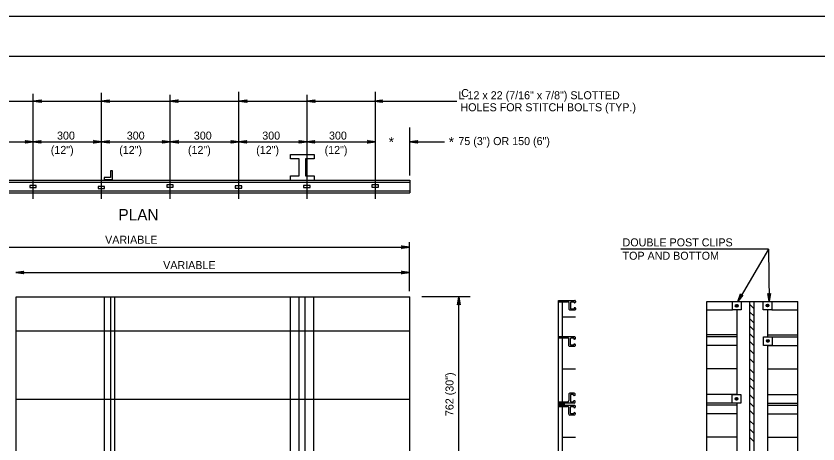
# Model space of a CAD drawing. Extents: x 647822 to 648727, y 298458 to 299646.
# Drawn here: x 647981.4 to 648281.8, y 299485.4 to 299645.6 of the extents above; entities that cross this region are included whole.
import ezdxf

# ---------------------------------------------------------------- set-up
doc = ezdxf.new("R2010")
doc.units = 0
for name, color, linetype in [('1', 7, 'Continuous'), ('2', 7, 'Continuous'), ('3', 7, 'Continuous'), ('XCS-GRID-MIN', 7, 'Continuous')]:
    doc.layers.add(name, color=color, linetype=linetype)

# ---------------------------------------------------------------- blocks, each defined once
blk = doc.blocks.new('RARROW')
at = {"layer": '3'}
blk.add_lwpolyline([(-2.2695, 0.285), (-2.184875, 0.12075), (0, 0), (-2.2695, 0.285), (-2.38575, 0.384625), (0, 0), (-2.183125, -0.108), (-2.262875, -0.2705), (0, 0), (-2.38575, -0.379125), (-2.262875, -0.2705)], dxfattribs=at)

msp = doc.modelspace()

# ---------------------------------------------------------------- linework, layer by layer
at = {"layer": '1'}
msp.add_line((647862.31, 299630.63), (648648.31, 299630.63), dxfattribs=at)
at = {"layer": '2'}
for p, q in [((647987.88, 299577.1), (647987.88, 299616.48)), ((648013.5, 299577.1), (648013.5, 299616.85)), ((648039.13, 299577.1), (648039.13, 299616.1)), ((648064.88, 299577.1), (648064.88, 299617.23)), ((648090.5, 299577.1), (648090.5, 299616.1)), ((648116.13, 299577.1), (648116.13, 299617.23)), ((647962.25, 299613.73), (647987.88, 299613.73)), ((647988, 299613.73), (648013.5, 299613.73)), ((647988, 299613.73), (647988, 299613.73)), ((648013.5, 299613.73), (648039.13, 299613.73)), ((648013.5, 299613.73), (648013.5, 299613.73)), ((648039.13, 299613.73), (648064.88, 299613.73)), ((648039.13, 299613.73), (648039.13, 299613.73)), ((648065, 299613.73), (648090.5, 299613.73)), ((648065, 299613.73), (648065, 299613.73)), ((648090.5, 299613.73), (648115.75, 299613.73)), ((648090.5, 299613.73), (648090.5, 299613.73)), ((648115.75, 299613.73), (648146.5, 299613.73)), ((648115.75, 299613.73), (648115.75, 299613.73)), ((648129, 299585.85), (648129, 299603.85)), ((647962.38, 299598.48), (647987.88, 299598.48)), ((647987.88, 299598.48), (648013.5, 299598.48)), ((648013.5, 299598.48), (648039.13, 299598.48)), ((648039.25, 299598.48), (648064.88, 299598.48)), ((648064.88, 299598.48), (648090.38, 299598.48)), ((648090.38, 299598.48), (648116.13, 299598.48)), ((648129, 299598.48), (648141.88, 299598.48)), ((648084.25, 299592.1), (648084.25, 299593.73)), ((648084.25, 299593.73), (648093.13, 299593.73)), ((648087.5, 299592.1), (648084.25, 299592.1)), ((648087.5, 299585.73), (648087.5, 299592.1)), ((648093.13, 299592.1), (648089.88, 299592.1)), ((648089.88, 299592.1), (648089.88, 299585.73)), ((648093.13, 299593.73), (648093.13, 299592.1)), ((648017.63, 299587.6), (648016.88, 299587.6)), ((648016.88, 299587.6), (648016.88, 299585.1)), ((648017.63, 299584.35), (648017.63, 299587.6)), ((647923.75, 299584.1), (648129, 299584.1)), ((647923.75, 299583.35), (648129, 299583.35)), ((648014.5, 299585.1), (648014.5, 299584.35)), ((648016.88, 299585.1), (648014.5, 299585.1)), ((648014.5, 299584.35), (648017.63, 299584.35)), ((648084.25, 299584.1), (648084.25, 299585.73)), ((648084.25, 299585.73), (648087.5, 299585.73)), ((648089.88, 299585.73), (648093.13, 299585.73)), ((648093.13, 299585.73), (648093.13, 299584.1)), ((648129.13, 299579.35), (648129.13, 299584.1)), ((647923.75, 299580.1), (648129, 299580.1)), ((647989, 299582.1), (647986.63, 299582.1)), ((647986.63, 299582.1), (647986.63, 299581.35)), ((647986.63, 299581.35), (647989, 299581.35)), ((647989, 299581.35), (647989, 299582.1)), ((648014.63, 299581.73), (648012.25, 299581.73)), ((648012.25, 299581.73), (648012.25, 299580.98)), ((648012.25, 299580.98), (648014.63, 299580.98)), ((648014.63, 299580.98), (648014.63, 299581.73)), ((648040.25, 299582.35), (648037.88, 299582.35)), ((648037.88, 299582.35), (648037.88, 299581.48)), ((648037.88, 299581.48), (648040.25, 299581.48)), ((648040.25, 299581.48), (648040.25, 299582.35)), ((648066, 299581.98), (648063.5, 299581.98)), ((648063.5, 299581.98), (648063.5, 299581.1)), ((648063.5, 299581.1), (648066, 299581.1)), ((648066, 299581.1), (648066, 299581.98)), ((648091.63, 299582.1), (648089.13, 299582.1)), ((648089.13, 299582.1), (648089.13, 299581.35)), ((648089.13, 299581.35), (648091.63, 299581.35)), ((648091.63, 299581.35), (648091.63, 299582.1)), ((648117.25, 299582.35), (648114.75, 299582.35)), ((648114.75, 299582.35), (648114.75, 299581.48)), ((648114.75, 299581.48), (648117.25, 299581.48)), ((648117.25, 299581.48), (648117.25, 299582.35)), ((647923.75, 299579.35), (648129, 299579.35)), ((647923.63, 299559.1), (648128.88, 299559.1)), ((648128.88, 299542.6), (648128.88, 299560.98)), ((648263.25, 299558.35), (648207.97, 299558.35)), ((648263.25, 299558.35), (648251.75, 299538.73)), ((648263.25, 299558.35), (648263.5, 299538.73)), ((647981.38, 299549.6), (648128.88, 299549.6)), ((647981.5, 299540.48), (648129, 299540.48)), ((647981.5, 299476.48), (647981.5, 299540.48)), ((648014.5, 299540.48), (648014.5, 299399.48)), ((648016.88, 299540.48), (648016.88, 299399.48)), ((648018.36, 299540.48), (648018.36, 299399.48)), ((648084.25, 299326.41), (648084.25, 299540.48)), ((648087.5, 299326.41), (648087.5, 299540.48)), ((648089.75, 299326.41), (648089.75, 299540.48)), ((648093, 299326.41), (648093, 299540.48)), ((648129, 299335.48), (648129, 299540.48)), ((648151.5, 299540.48), (648133.5, 299540.48)), ((648147.25, 299476.23), (648147.25, 299540.48)), ((648184.63, 299335.43), (648184.63, 299539.1)), ((648184.63, 299539.1), (648190.74, 299539.1)), ((648184.63, 299538.6), (648188, 299538.6)), ((648186.13, 299335.43), (648186.13, 299539.1)), ((648188.63, 299535.74), (648188.63, 299538.1)), ((648189.25, 299536.01), (648189.25, 299538.44)), ((648189.41, 299538.6), (648190.34, 299538.6)), ((648190.5, 299538.44), (648190.5, 299538.39)), ((648190.66, 299538.23), (648190.74, 299538.23)), ((648190.75, 299538.23), (648190.75, 299538.23)), ((648191, 299538.84), (648191, 299538.49)), ((648240.25, 299335.47), (648240.25, 299538.73)), ((648240.25, 299538.73), (648274.25, 299538.73)), ((648249.75, 299535.6), (648249.75, 299538.73)), ((648253, 299538.73), (648253, 299535.6)), ((648256.25, 299335.47), (648256.25, 299538.73)), ((648257.88, 299335.47), (648257.88, 299538.73)), ((648261.25, 299538.73), (648264.5, 299538.73)), ((648261.25, 299535.6), (648261.25, 299538.73)), ((648264.5, 299538.73), (648264.5, 299535.6)), ((648274.25, 299335.47), (648274.25, 299538.73)), ((648190.74, 299535.48), (648188.89, 299535.48)), ((648190.34, 299535.85), (648189.41, 299535.85)), ((648190.5, 299536.21), (648190.5, 299536.01)), ((648190.84, 299536.37), (648190.66, 299536.37)), ((648191, 299536.21), (648191, 299535.74)), ((648240.25, 299535.6), (648249.75, 299535.6)), ((648253, 299535.6), (648249.75, 299535.6)), ((648251.38, 299535.6), (648251.38, 299535.6)), ((648251.5, 299503.85), (648251.5, 299535.6)), ((648257.88, 299535.98), (648256.25, 299537.6)), ((648264.5, 299535.6), (648261.25, 299535.6)), ((648262.88, 299535.6), (648262.88, 299535.6)), ((648263, 299525.48), (648263, 299535.6)), ((648264.5, 299535.6), (648274.25, 299535.6)), ((648186.13, 299532.98), (648191, 299532.98)), ((648257.88, 299533.23), (648256.25, 299534.73)), ((648257.88, 299530.6), (648256.25, 299532.23)), ((648257.88, 299527.85), (648256.25, 299529.48)), ((647981.5, 299527.73), (648129, 299527.73)), ((648251.5, 299526.23), (648240.25, 299526.23)), ((648257.88, 299524.98), (648256.25, 299526.6)), ((648263, 299526.23), (648274.25, 299526.23)), ((648184.63, 299525.6), (648190.62, 299525.6)), ((648184.63, 299525.1), (648188.24, 299525.1)), ((648188.5, 299522.11), (648188.5, 299524.84)), ((648189.13, 299522.51), (648189.13, 299524.84)), ((648189.39, 299525.1), (648190.22, 299525.1)), ((648190.38, 299524.94), (648190.38, 299524.75)), ((648190.72, 299524.59), (648190.54, 299524.59)), ((648190.88, 299525.34), (648190.88, 299524.75)), ((648251.5, 299525.48), (648240.25, 299525.48)), ((648257.88, 299522.1), (648256.25, 299523.73)), ((648261.38, 299525.48), (648264.63, 299525.48)), ((648261.38, 299522.23), (648261.38, 299525.48)), ((648263, 299525.48), (648274.25, 299525.48)), ((648263, 299525.48), (648263, 299525.48)), ((648264.63, 299525.48), (648264.63, 299522.23)), ((648190.62, 299521.85), (648188.76, 299521.85)), ((648190.22, 299522.35), (648189.29, 299522.35)), ((648190.38, 299522.58), (648190.38, 299522.51)), ((648190.72, 299522.74), (648190.54, 299522.74)), ((648190.88, 299522.58), (648190.88, 299522.11)), ((648251.5, 299522.23), (648240.25, 299522.23)), ((648257.88, 299518.98), (648256.25, 299520.6)), ((648264.63, 299522.23), (648261.38, 299522.23)), ((648263, 299522.35), (648263, 299522.35)), ((648263, 299522.23), (648274.25, 299522.23)), ((648263, 299478.85), (648263, 299522.23)), ((648257.88, 299515.6), (648256.25, 299517.23)), ((648186.13, 299513.48), (648191, 299513.48)), ((648251.5, 299513.48), (648240.25, 299513.48)), ((648257.88, 299511.73), (648256.25, 299513.35)), ((648263, 299513.48), (648274.25, 299513.48)), ((648257.88, 299508.6), (648256.25, 299510.1)), ((648257.88, 299505.6), (648256.25, 299507.23)), ((647981.5, 299502.1), (648129, 299502.1)), ((648188.5, 299504.1), (648188.5, 299501.6)), ((648190.5, 299504.35), (648188.88, 299504.35)), ((648189.13, 299503.73), (648189.13, 299501.23)), ((648190.13, 299503.85), (648189.25, 299503.85)), ((648190.25, 299503.6), (648190.25, 299503.73)), ((648190.63, 299503.48), (648190.5, 299503.48)), ((648190.88, 299503.6), (648190.88, 299504.1)), ((648251.5, 299503.85), (648240.25, 299503.85)), ((648249.63, 299503.85), (648252.88, 299503.85)), ((648249.63, 299500.6), (648249.63, 299503.85)), ((648251.25, 299503.85), (648251.25, 299503.85)), ((648252.88, 299503.85), (648252.88, 299500.6)), ((648257.88, 299502.1), (648256.25, 299503.73)), ((648263, 299503.85), (648274.25, 299503.85)), ((648184.63, 299501.1), (648187.88, 299501.1)), ((648184.63, 299500.73), (648190.5, 299500.73)), ((648184.63, 299499.85), (648190.63, 299499.85)), ((648184.63, 299499.35), (648187.88, 299499.35)), ((648188.5, 299496.48), (648188.5, 299498.85)), ((648189.13, 299496.73), (648189.13, 299499.23)), ((648189.25, 299501.1), (648190.13, 299501.1)), ((648189.25, 299499.35), (648190.13, 299499.35)), ((648190.25, 299501.23), (648190.25, 299501.35)), ((648190.38, 299499.23), (648190.38, 299499.1)), ((648190.5, 299501.6), (648190.63, 299501.6)), ((648190.63, 299498.98), (648190.63, 299498.98)), ((648190.88, 299500.98), (648190.88, 299501.35)), ((648190.88, 299499.6), (648190.88, 299499.1)), ((648251.5, 299500.6), (648240.25, 299500.6)), ((648251.5, 299499.85), (648240.25, 299499.85)), ((648252.88, 299500.6), (648249.63, 299500.6)), ((648251.25, 299500.6), (648251.25, 299500.6)), ((648251.5, 299453.1), (648251.5, 299500.6)), ((648257.88, 299499.1), (648256.25, 299500.73)), ((648263, 299500.6), (648274.25, 299500.6)), ((648263, 299499.85), (648274.25, 299499.85)), ((648190.63, 299496.1), (648188.88, 299496.1)), ((648190.13, 299496.6), (648189.25, 299496.6)), ((648190.38, 299496.85), (648190.38, 299496.73)), ((648190.63, 299497.1), (648190.63, 299497.1)), ((648190.88, 299496.85), (648190.88, 299496.48)), ((648251.5, 299496.6), (648240.25, 299496.6)), ((648257.88, 299496.23), (648256.25, 299497.85)), ((648263, 299496.6), (648274.25, 299496.6)), ((648257.88, 299492.48), (648256.25, 299493.98)), ((648257.88, 299489.23), (648256.25, 299490.85)), ((648186.13, 299487.85), (648191, 299487.85)), ((648251.5, 299487.85), (648240.25, 299487.85)), ((648257.88, 299486.1), (648256.25, 299487.73)), ((648263, 299487.85), (648274.25, 299487.85))]:
    msp.add_line(p, q, dxfattribs=at)
for points in [[(648251.25, 299537.48), (648251.13, 299537.23), (648251.13, 299536.85), (648251.38, 299536.73), (648251.63, 299536.85), (648251.75, 299537.1), (648251.75, 299537.35), (648251.63, 299537.48), (648251.38, 299537.48), (648251.25, 299537.23), (648251.25, 299537.1), (648251.25, 299536.98), (648251.38, 299536.98), (648251.5, 299537.1), (648251.63, 299537.23), (648251.5, 299537.35), (648251.5, 299537.23), (648251.38, 299537.1)], [(648262.75, 299537.6), (648262.63, 299537.23), (648262.63, 299536.98), (648262.88, 299536.85), (648263.13, 299536.98), (648263.25, 299537.23), (648263.25, 299537.48), (648263.13, 299537.6), (648262.88, 299537.48), (648262.75, 299537.23), (648262.75, 299537.1), (648262.75, 299537.1), (648262.88, 299536.98), (648263, 299537.23), (648263.13, 299537.23), (648263, 299537.48), (648263, 299537.35), (648262.88, 299537.1)], [(648262.88, 299524.35), (648262.75, 299523.98), (648262.75, 299523.73), (648263, 299523.48), (648263.25, 299523.6), (648263.38, 299523.85), (648263.38, 299524.1), (648263.25, 299524.35), (648263.13, 299524.23), (648262.88, 299523.98), (648262.88, 299523.85), (648262.88, 299523.73), (648263, 299523.73), (648263.13, 299523.85), (648263.25, 299523.98), (648263.25, 299524.1), (648263.13, 299523.98), (648263, 299523.85)], [(648251.25, 299502.6), (648251, 299502.35), (648251, 299501.98), (648251.25, 299501.85), (648251.5, 299501.98), (648251.63, 299502.23), (648251.63, 299502.48), (648251.5, 299502.6), (648251.38, 299502.6), (648251.13, 299502.35), (648251.13, 299502.23), (648251.13, 299502.1), (648251.38, 299502.1), (648251.5, 299502.23), (648251.5, 299502.35), (648251.5, 299502.48), (648251.38, 299502.35), (648251.25, 299502.23)], [(648186.75, 299500.98), (648186.75, 299499.6), (648184.88, 299499.6), (648184.75, 299500.98), (648186.25, 299500.73), (648186.38, 299500.85), (648186.38, 299499.85), (648185.13, 299499.85), (648185.13, 299500.48), (648185.88, 299500.6), (648186, 299500.1), (648185.38, 299500.1), (648185.38, 299500.98), (648186.25, 299500.98), (648186.25, 299500.73)]]:
    msp.add_lwpolyline(points, dxfattribs=at)
for centre in [(648251.38, 299537.06), (648262.91, 299537.23), (648263.06, 299523.97), (648251.34, 299502.26)]:
    msp.add_circle(centre, 0.525, dxfattribs=at)
for centre, radius, start, end in [((648189.41, 299538.44), 0.16, 90, 180), ((648190.34, 299538.44), 0.16, 0, 90), ((648190.66, 299538.39), 0.16, 180, 270), ((648190.74, 299538.84), 0.26, 0, 90), ((648190.74, 299538.49), 0.26, 270, 0), ((648188.89, 299535.74), 0.26, 180, 270), ((648189.41, 299536.01), 0.16, 180, 270), ((648190.34, 299536.01), 0.16, 270, 0), ((648190.66, 299536.21), 0.16, 90, 180), ((648190.74, 299535.74), 0.26, 270, 0), ((648190.84, 299536.21), 0.16, 0, 90), ((648188.24, 299524.84), 0.26, 0, 90), ((648189.39, 299524.84), 0.26, 90, 180), ((648190.22, 299524.94), 0.16, 0, 90), ((648190.54, 299524.75), 0.16, 180, 270), ((648190.62, 299525.34), 0.26, 0, 90), ((648190.72, 299524.75), 0.16, 270, 0), ((648188.76, 299522.11), 0.26, 180, 270), ((648189.29, 299522.51), 0.16, 180, 270), ((648190.22, 299522.51), 0.16, 270, 0), ((648190.54, 299522.58), 0.16, 90, 180), ((648190.62, 299522.11), 0.26, 270, 0), ((648190.72, 299522.58), 0.16, 0, 90)]:
    msp.add_arc(centre, radius, start, end, dxfattribs=at)
for centre, major_axis, start_param, end_param in [((648187.98, 299538.08), (0.653, 0), 0, 1.570796), ((648188.84, 299504.09), (-0.327, 0), 4.712389, 6.283185), ((648189.25, 299503.76), (-0.163, 0), 4.712389, 6.283185), ((648190.14, 299503.76), (-0.163, 0), 3.141593, 4.712389), ((648190.56, 299503.64), (0.251, 0), 3.141593, 4.712389), ((648190.56, 299504.09), (0.327, 0), 0, 1.570796), ((648190.63, 299503.64), (0.251, 0), 4.712389, 6.283185), ((648187.86, 299501.65), (0.653, 0), 4.712389, 6.283185), ((648187.88, 299498.88), (0.653, 0), 0, 1.570796), ((648189.25, 299501.25), (0.163, 0), 3.141593, 4.712389), ((648189.27, 299499.27), (-0.163, 0), 4.712389, 6.283185), ((648190.14, 299501.25), (0.163, 0), 4.712389, 6.283185), ((648190.17, 299499.27), (0.163, 0), 0, 1.570796), ((648190.56, 299501.39), (-0.251, 0), 4.712389, 6.283185), ((648190.58, 299499.14), (-0.251, 0), 0, 1.570796), ((648190.56, 299500.93), (0.327, 0), 4.712389, 6.283185), ((648190.58, 299499.6), (0.327, 0), 0, 1.570796), ((648190.63, 299501.39), (0.251, 0), 0, 1.570796), ((648190.66, 299499.14), (0.251, 0), 4.712389, 6.283185), ((648188.86, 299496.43), (0.327, 0), 3.141593, 4.712389), ((648189.27, 299496.76), (-0.163, 0), 0, 1.570796), ((648190.17, 299496.76), (0.163, 0), 4.712389, 6.283185), ((648190.58, 299496.89), (-0.251, 0), 4.712389, 6.283185), ((648190.58, 299496.43), (0.327, 0), 4.712389, 6.283185), ((648190.66, 299496.89), (-0.251, 0), 3.141593, 4.712389)]:
    msp.add_ellipse(centre, major_axis=major_axis, ratio=0.806863, start_param=start_param, end_param=end_param, dxfattribs=at)
at = {"layer": 'XCS-GRID-MIN'}
msp.add_lwpolyline([(647822.31, 299645.63), (648663.31, 299645.63), (648663.31, 299051.63), (647822.31, 299051.63)], close=True, dxfattribs=at)

# ---------------------------------------------------------------- block references
at = {"layer": '2', "xscale": 1.2574347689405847, "yscale": 1.3092961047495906}
for p, rotation in [((647988, 299613.73), 180), ((648013.5, 299613.73), 180), ((648039.13, 299613.73), 180), ((648065, 299613.73), 180), ((648090.5, 299613.73), 180), ((648115.75, 299613.73), 180), ((647987.88, 299598.48), 180), ((648013.5, 299598.48), 180), ((648039.25, 299598.48), 180), ((648064.88, 299598.48), 180), ((648090.38, 299598.48), 180), ((648129, 299598.48), 180), ((647981.38, 299549.6), 180), ((648251.75, 299538.73), -119.77918658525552), ((648263.5, 299538.73), -90.00000000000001), ((648147.25, 299540.48), 89.99999999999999)]:
    msp.add_blockref('RARROW', p, dxfattribs=dict(at, rotation=rotation))
for p in [(647987.88, 299598.48), (648013.5, 299598.48), (648039.13, 299598.48), (648064.88, 299598.48), (648090.38, 299598.48), (648116.13, 299598.48), (648128.88, 299559.1), (648128.88, 299549.6)]:
    msp.add_blockref('RARROW', p, dxfattribs=at)

# ---------------------------------------------------------------- texts
at = {"layer": '2'}
for s, height, p in [(' L 12 x 22 (7/16" x 7/8") SLOTTED', 3, (648146.09, 299614.46)), ('C', 3, (648148.19, 299615.28)), (' HOLES FOR STITCH BOLTS (TYP.)', 3, (648146.79, 299609.96)), ('300', 3, (647996.79, 299599.35)), ('300', 3, (648022.92, 299599.35)), ('300', 3, (648048.04, 299599.35)), ('300', 3, (648073.67, 299599.35)), ('300', 3, (648098.67, 299599.35)), ('*', 3.87, (648121, 299596.48)), ('*', 3.87, (648143.5, 299596.48)), ('75 (3") OR 150 (6")', 3, (648147.13, 299597.29)), ('(12")', 3, (647994.45, 299593.98)), ('(12")', 3, (648020.08, 299593.98)), ('(12")', 3, (648045.83, 299593.98)), ('(12")', 3, (648071.39, 299593.98)), ('(12")', 3, (648097.02, 299593.98)), ('PLAN', 4.3, (648019.8, 299569.05)), ('VARIABLE', 3, (648014.8, 299560.35)), ('DOUBLE POST CLIPS', 3, (648208.63, 299559.35)), ('TOP AND BOTTOM', 3, (648208.63, 299554.35)), ('VARIABLE', 3, (648036.55, 299550.85))]:
    msp.add_text(s, height=height, dxfattribs=at).set_placement(p)
msp.add_text('762 (30")', height=3, rotation=90, dxfattribs=at).set_placement((648145.3, 299495.78))

doc.saveas('drawing.dxf')
